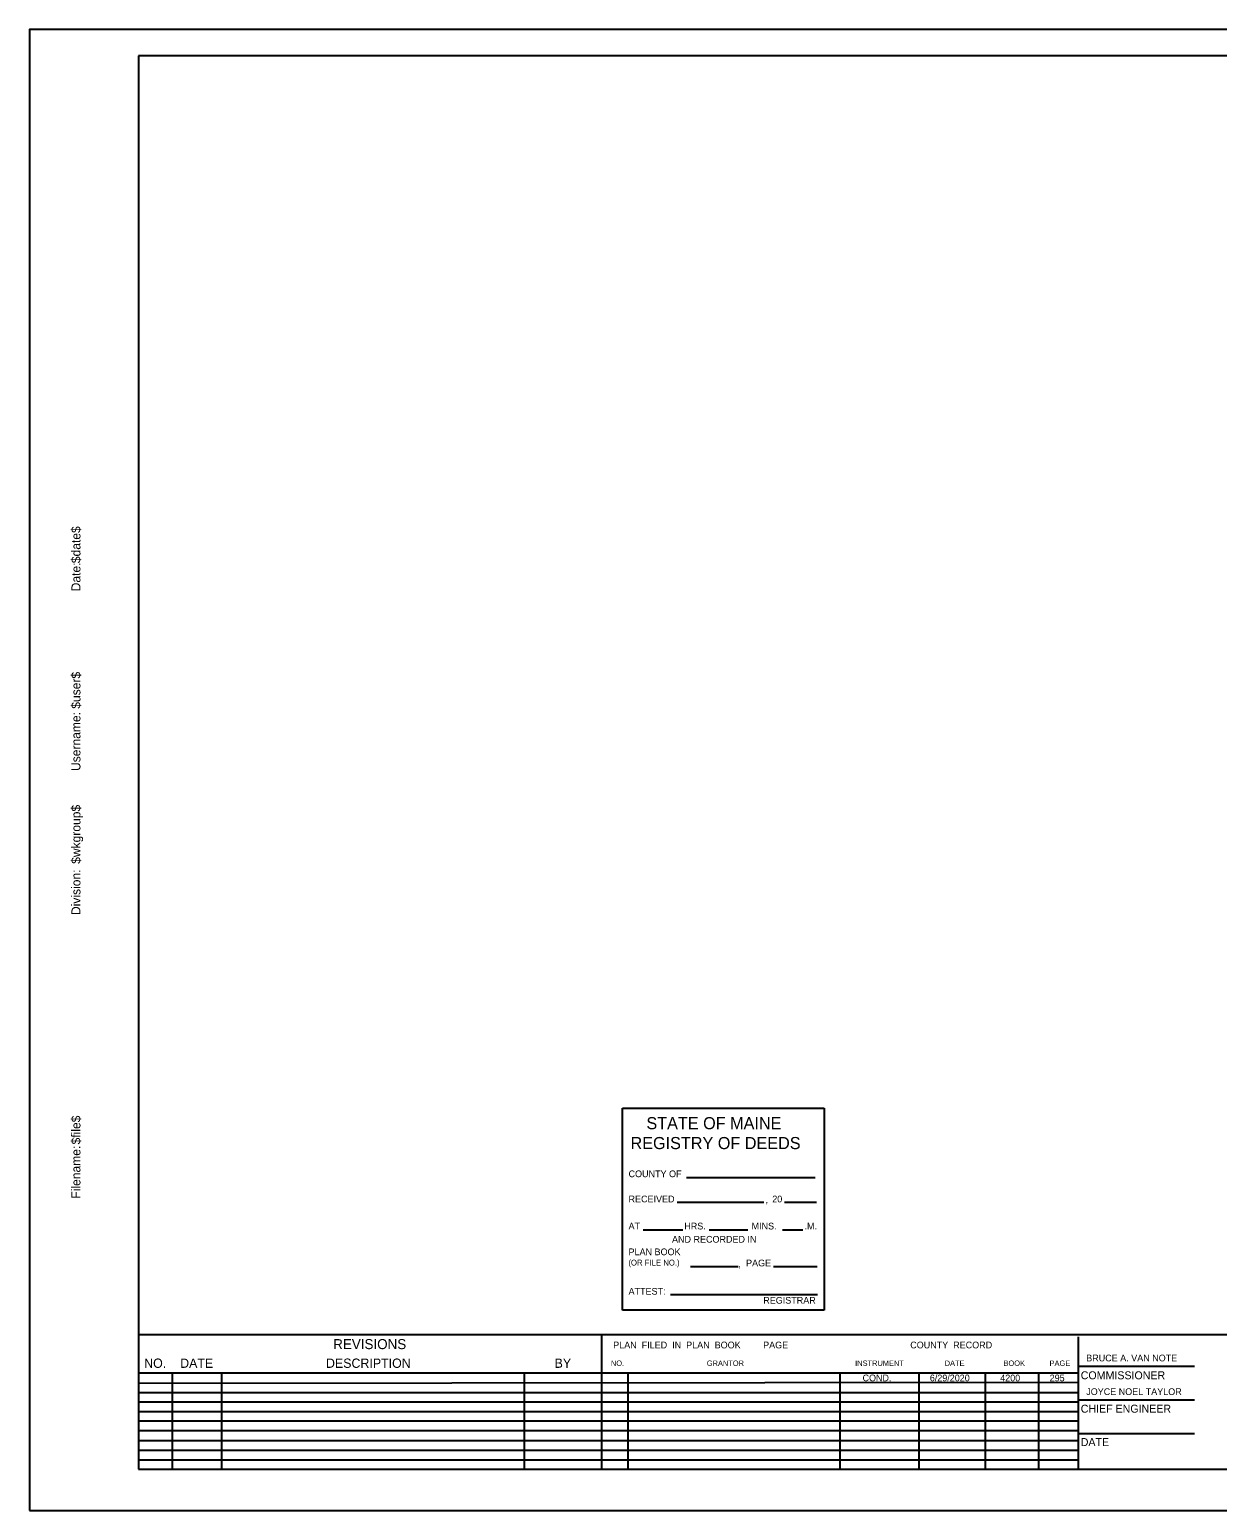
# Model space of a CAD drawing. Extents: x -415 to 435, y -303 to 247.
# Drawn here: x -415 to 26, y -303 to 247 of the extents above; entities that cross this region are included whole.
import ezdxf

# ---------------------------------------------------------------- set-up
doc = ezdxf.new("R2010")
doc.units = 0
for name, color, linetype in [('Border', 7, 'Continuous'), ('EX ROW NOTES', 7, 'Continuous'), ('PLOT BOUNDARY', 7, 'Continuous'), ('PRPTY SETUPS', 7, 'Continuous')]:
    doc.layers.add(name, color=color, linetype=linetype)

msp = doc.modelspace()

# ---------------------------------------------------------------- linework, layer by layer
at = {"layer": 'Border'}
for p, q in [((425, 237.5), (-375, 237.5)), ((-375, 237.5), (-375, -287.5)), ((-375, -237.49), (425, -237.49)), ((-202.99, -237.49), (-202.99, -287.5)), ((-25.83, -238.29), (-25.83, -287.5)), ((-375, -251.67), (-25.83, -251.67)), ((-362.5, -251.67), (-362.5, -287.5)), ((-344.13, -251.67), (-344.13, -287.5)), ((-231.63, -251.67), (-231.63, -287.5)), ((-193.15, -251.67), (-193.15, -287.5)), ((-114.41, -251.67), (-114.41, -287.5)), ((-84.88, -287.5), (-84.88, -251.67)), ((-60.27, -287.5), (-60.27, -251.67)), ((-40.59, -251.67), (-40.59, -287.5)), ((-25.83, -249.2), (17.41, -249.2)), ((-375, -255.6), (-25.83, -255.22)), ((-375, -258.96), (-25.83, -258.96)), ((-375, -262.5), (-26.02, -262.5)), ((-25.83, -261.7), (17.41, -261.7)), ((-375, -266.04), (-25.83, -266.04)), ((-375, -269.59), (-25.83, -269.59)), ((-375, -273.13), (-25.63, -273.13)), ((-25.83, -274.2), (17.41, -274.2)), ((-375, -276.87), (-25.83, -276.87)), ((-375, -280.41), (-25.83, -280.41)), ((-375, -283.96), (-25.83, -283.96)), ((-375, -287.5), (425, -287.5))]:
    msp.add_line(p, q, dxfattribs=at)
at = {"layer": 'PLOT BOUNDARY'}
msp.add_lwpolyline([(-415.47, -302.8), (434.53, -302.8), (434.53, 247.2), (-415.47, 247.2)], close=True, dxfattribs=at)
at = {"layer": 'PRPTY SETUPS'}
for p, q in [((-195.16, -153.44), (-120.18, -153.44)), ((-195.16, -228.42), (-195.16, -153.44)), ((-120.18, -153.44), (-120.18, -228.42)), ((-171.34, -179.2), (-123.61, -179.2)), ((-174.89, -188.36), (-142.65, -188.36)), ((-134.93, -188.36), (-123.08, -188.36)), ((-187.46, -198.65), (-172.68, -198.65)), ((-162.93, -198.65), (-148.56, -198.65)), ((-135.73, -198.65), (-128.18, -198.65)), ((-169.86, -212.16), (-152.15, -212.16)), ((-139.02, -212.16), (-122.84, -212.16)), ((-177.28, -222.61), (-122.75, -222.61)), ((-120.18, -228.42), (-195.16, -228.42))]:
    msp.add_line(p, q, dxfattribs=at)

# ---------------------------------------------------------------- texts
at = {"layer": 'Border'}
for s, height, rotation, p in [('$date$', 3.348, 90, (-396.58, 49.03)), ('Date:', 3.348, 90, (-396.58, 38.58)), ('$user$', 3.348, 90, (-396.58, -5.04)), ('Username:', 3.348, 90, (-396.58, -28.16)), ('$wkgroup$', 3.348, 90, (-396.58, -62.65)), ('Division:', 3.348, 90, (-396.58, -81.67)), ('$file$', 3.348, 90, (-396.58, -166.87)), ('Filename:', 3.348, 90, (-396.58, -187.01)), ('REVISIONS', 3.726, 360, (-302.65, -242.9)), ('NO.', 3.445, 360, (-372.89, -249.85)), ('DATE', 3.445, 360, (-359.52, -249.85)), ('DESCRIPTION', 3.4449, 360, (-305.33, -249.85)), ('BY', 3.445, 360, (-220.38, -249.85)), ('COMMISSIONER', 2.9528, 360, (-24.87, -254.1)), ('CHIEF ENGINEER', 2.9528, 360, (-24.87, -266.5)), ('DATE', 2.953, 360, (-24.87, -278.9))]:
    msp.add_text(s, height=height, rotation=rotation, dxfattribs=at).set_placement(p)
for s, height, p in [('PLAN  FILED  IN  PLAN  BOOK         PAGE', 2.4992, (-198.6, -242.62)), ('COUNTY  RECORD', 2.4992, (-88.23, -242.62)), ('NO.', 2, (-199.45, -249.13)), ('GRANTOR', 2, (-163.82, -249.13)), ('INSTRUMENT', 2, (-108.7, -249.13)), ('DATE', 2, (-75.43, -249.13)), ('BOOK', 2, (-53.58, -249.13)), ('PAGE', 2, (-36.46, -249.13)), ('BRUCE A. VAN NOTE', 2.5, (-22.83, -247.45)), ('JOYCE NOEL TAYLOR', 2.5, (-22.83, -259.95))]:
    msp.add_text(s, height=height, dxfattribs=at).set_placement(p)
at = {"layer": 'EX ROW NOTES'}
for s, p in [('COND.', (-105.94, -254.84)), ('6/29/2020', (-80.94, -254.84)), ('4200', (-54.78, -254.84)), ('295', (-36.41, -254.84))]:
    msp.add_text(s, height=2.49, dxfattribs=at).set_placement(p)
at = {"layer": 'PRPTY SETUPS'}
for s, height, p in [('STATE OF MAINE', 4.5, (-186.26, -161.22)), ('REGISTRY OF DEEDS', 4.5, (-192.17, -168.61)), ('COUNTY OF', 2.5, (-192.9, -179.04)), ('RECEIVED', 2.5, (-192.9, -188.39)), ('20', 2.5, (-139.5, -188.39)), (',', 2.61, (-142.04, -188.61)), ('AT', 2.5, (-192.9, -198.45)), ('HRS.', 2.5, (-172.19, -198.45)), ('MINS.', 2.5, (-147.18, -198.45)), ('.M.', 2.5, (-127.51, -198.45)), ('AND RECORDED IN', 2.5, (-176.75, -203.35)), ('PLAN BOOK ', 2.5, (-192.9, -208.02)), ('(OR FILE NO.)', 2.1531, (-192.97, -211.85)), (',', 2.61, (-152.1, -212.48)), ('PAGE', 2.5, (-149.23, -212.16)), ('ATTEST:', 2.5, (-192.9, -222.67)), ('REGISTRAR', 2.5, (-142.84, -226.02))]:
    msp.add_text(s, height=height, dxfattribs=at).set_placement(p)

doc.saveas('drawing.dxf')
